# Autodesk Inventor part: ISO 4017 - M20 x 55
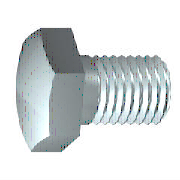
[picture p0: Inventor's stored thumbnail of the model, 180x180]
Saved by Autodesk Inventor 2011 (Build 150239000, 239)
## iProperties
IsCustomPart: 0
Created: 2010-02
Part Number: ISO 4017 - M20 x 55
Material: Stainless Steel, 440C
Description: Hexagon head screws
Document SubType Name: Modeling
Standard: ISO 4017
Designer: 129877
Standard Revision: Third edition 1999-08-15
Standards Organization: ISO
Language: en-US
Size Designation: M20 x 55
Categories: <MemberInstance><Categories><Category DisplayName="Fasteners" InternalName="e4da775c-781d-43d5-af7c-5136215cf5a6" Mnemonic="FSTN"><Category DisplayName="Bolts"
Density: 7.75 g/cm^3
Mass: 207.684 g
Surface Area: 62.0532 cm^2
Volume: 26.798 cm^3
Author: 129877
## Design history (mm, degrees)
body "Solid1"
workplane "Work Plane1"
revolve "Body" stored, may be unused: angle "d12" = 90 deg
sketch "Sketch2"
  geometry: L1 (0, 17.321)-(15, 8.66); L2 (15, 8.66)-(15, -8.66); L3 (15, -8.66)-(0, -17.321); L4 (0, -17.321)-(-15, -8.66); L5 (-15, -8.66)-(-15, 8.66); L6 (-15, 8.66)-(0, 17.321); 2 further points
  constraints: 12 end point, 1 coincident, 1 vertical, 11 other
  dimensions: "d11" = 30 distance between parallel lines of L5 L2 (= SW)
extrude "Head" join sketch "Sketch2" distance "d3" = 11.7 (= KOH - SD); taper "d4" = 0 deg
revolve "Chamfer1" stored, may be unused: angle "d21" = 90 deg
feature "Thread" dims "d15" = 47.5 (= GEL), "d16" = 0
chamfer "Chamfer2" distance "d6" = 1.53363 (= -0.5 x SPD + 0.5 x GD); stored, may be unused: second distance "d7" = 1.53373 (computed from GUL), angle "d55" = 45 deg
sketch "Sketch1"
  geometry: L1 (0, 14.095)-(0, 10); L2 (7.5, 10)-(55, 10); L3 (55, 10)-(55, 0); L4 (55, 0)-(-0.8, 0); L5 (-11.96, 0)-(66.16, 0) reference; L6 (-0.8, 0)-(-0.8, 14.095); L7 (-0.8, 14.095)-(0, 14.095); L8 (7.5, 10)-(5.966, 10); L9 (5.966, 10)-(0, 10); L10 (0, -2.819)-(0, 16.914) reference
  constraints: 16 end point, 2 collinear, 2 perpendicular, 1 parallel
  dimensions: "d0" = 55 distance between parallel lines of L3 L1 (= NLG); "d1" = 47.5 distance from line of L2.start L3 (= GEL); "d2" = 20 diameter of L2 L4 (= GD); "d9" = 0.8001 distance between parallel lines of L6 L1 (computed from SD); "d10" = 28.19 diameter of L7 L4 (= SD2); "d13" = 1.53373 distance of L2.start L8.end (computed from GAL); "d14" = 20 diameter of L9 L4 (= BDM)
sketch "Sketch4"
  geometry: L1 (-12.5, 15)-(-12.5, 17.321); L2 (-12.5, 17.321)-(-11.16, 17.321); L3 (-11.16, 17.321)-(-12.5, 15); L4 (-14.84, 0)-(1.54, 0) reference; L5 (-0.8, 17.321)-(-12.5, 17.321) reference; L6 (-12.5, 8.66)-(-12.5, 17.321) reference
  constraints: 6 end point, 2 collinear, 1 perpendicular, 1 vertical
  dimensions: "d5" = 30 deg angle of L3 L1 (= ANG1); "d19" = 30 diameter of L1.start L4 (= SW0)
other parameters: "NLG" = 55 [user parameter; used in 1 equation term], "GD" = 20 (= NND) [user parameter; used in 2 equation terms], "BDM" = 20 (= NND) [user parameter; used in 1 equation term], "KOH" = 12.5 [user parameter; used in 1 equation term], "GEL" = 47.5 [user parameter; used in 2 equation terms], "SW" = 30 [user parameter; used in 2 equation terms], "SW0" = 30 (= SW) [user parameter; used in 1 equation term], "SPD" = 16.93275 (= NND - 1.2269 x PTC) [user parameter; used in 1 equation term], "SD2" = 28.19 [user parameter; used in 2 equation terms], "SD" = 0.8 [user parameter; used in 2 equation terms], "ANG1" = 30 deg [user parameter; used in 1 equation term], "GAL" = 1.53363 (= 0.61345 x PTC) [user parameter; used in 1 equation term], "GUL" = 1.53363 (= 0.61345 x PTC) [user parameter; used in 1 equation term], "d8" = 0, "RR" = 0.8 [user parameter], "d57" = 0, "d58" = 0, "TPU" = 4 (computed from PTC) [user parameter], "GD1" = 16.93275 (= THREADDIA - 1.2269 x PTC) [user parameter], "SDH" = 28.19 (= SD2) [user parameter], "SDHG" = 7.5 [user parameter], "TOA" = 30 deg [user parameter], "PTC" = 2.5 [user parameter; used in 5 equation terms], "E0" = 34.65 [user parameter]
